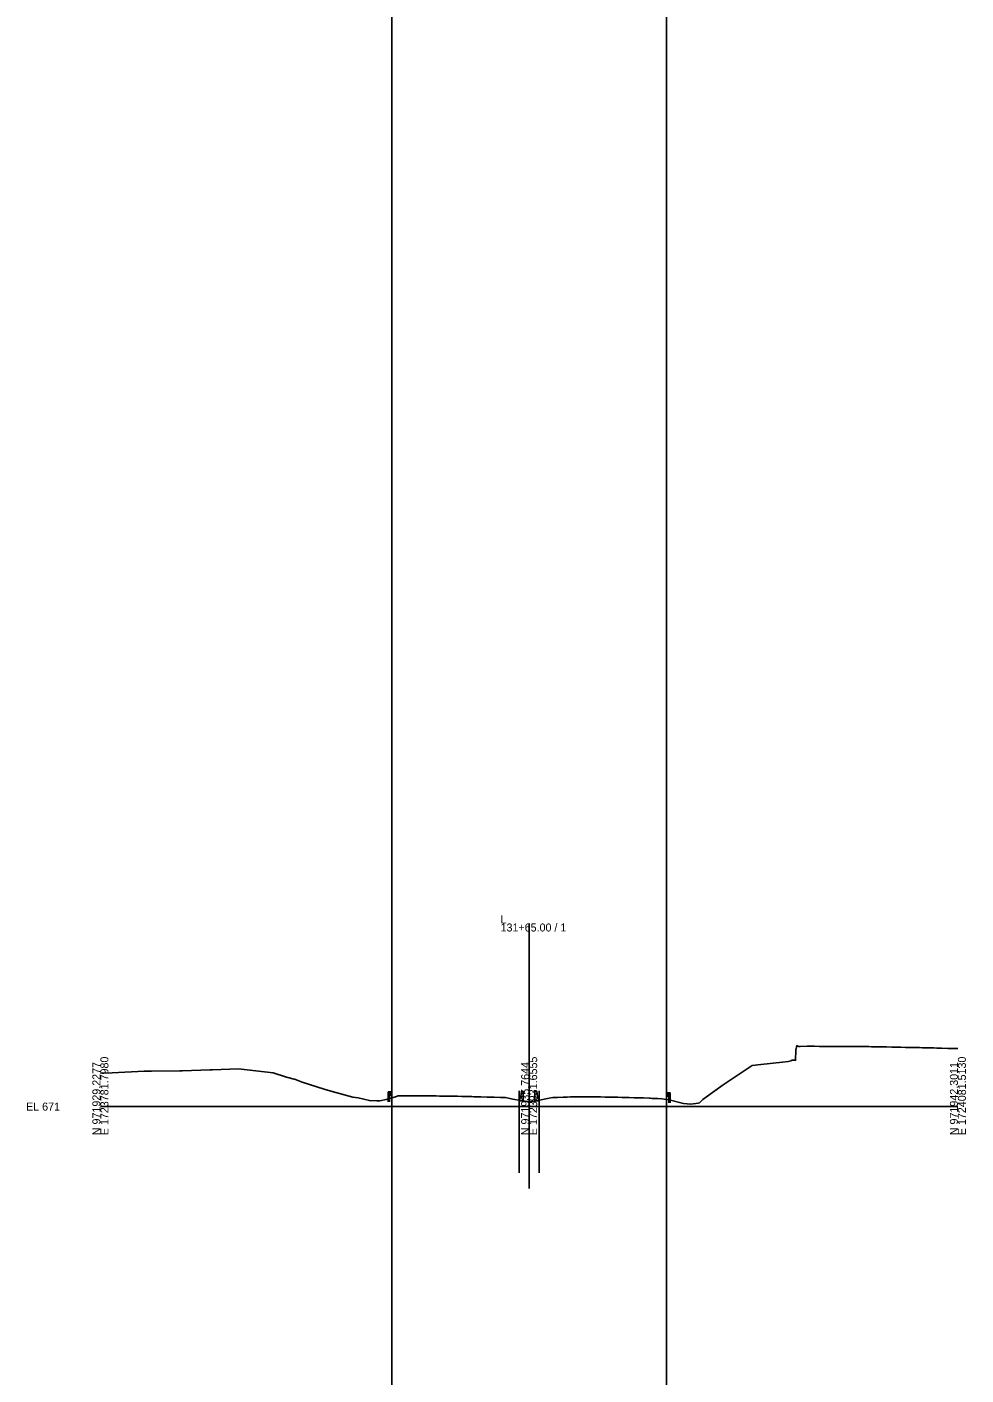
# Model space of a CAD drawing. Extents: x -26 to 303, y -29 to 15026.
# Drawn here: x -25.7 to 302.8, y 5906.1 to 6377.7 of the extents above; entities that cross this region are included whole.
import ezdxf

# ---------------------------------------------------------------- set-up
doc = ezdxf.new("R2010")
doc.units = 0
for name, color, linetype in [('Exist Cross Section Cell', 7, 'Continuous'), ('Exist XS Center Line Elevation Label', 7, 'Continuous'), ('Exist XS Ground Line', 7, 'Continuous'), ('Scratch_Level_0', 7, 'Continuous'), ('Typical Guardrail CELL', 7, 'Continuous'), ('Typical Median Barrier CELL', 7, 'Continuous')]:
    doc.layers.add(name, color=color, linetype=linetype)

msp = doc.modelspace()

# ---------------------------------------------------------------- linework, layer by layer
at = {"layer": 'Exist Cross Section Cell'}
for p, q in [((150, 6000), (150, 6064.05)), ((0, 6000), (150, 6000)), ((150, 6000), (300, 6000))]:
    msp.add_line(p, q, dxfattribs=at)
at = {"layer": 'Exist XS Ground Line'}
msp.add_lwpolyline([(0, 6011.68), (4.14, 6011.84), (15.31, 6012.44), (17.82, 6012.43), (27.8, 6012.49), (28.24, 6012.51), (28.72, 6012.54), (38.25, 6012.82), (39.19, 6012.85), (48.26, 6013.23), (51.3, 6012.91), (60.43, 6011.87), (65.15, 6010.32), (68.28, 6009.45), (70.58, 6008.59), (78.29, 6006.1), (81.05, 6005.3), (88.29, 6003.29), (90.14, 6003.1), (94.14, 6002.12), (96.69, 6001.96), (97.71, 6001.99), (99.94, 6002.52), (103.23, 6003.42), (104.12, 6003.71), (104.95, 6003.78), (105.63, 6003.79), (107.4, 6003.79), (109.09, 6003.78), (109.93, 6003.78), (110.74, 6003.78), (111.28, 6003.78), (111.68, 6003.78), (112.43, 6003.77), (113.47, 6003.75), (114.93, 6003.73), (116.07, 6003.72), (117.42, 6003.71), (118.66, 6003.7), (119.91, 6003.68), (121.26, 6003.66), (122.4, 6003.65), (123.06, 6003.64), (123.92, 6003.62), (124.9, 6003.61), (126.49, 6003.56), (127.4, 6003.54), (129.13, 6003.5), (129.91, 6003.48), (130.62, 6003.46), (132.43, 6003.42), (133.04, 6003.4), (135.18, 6003.34), (135.74, 6003.32), (137.06, 6003.29), (137.41, 6003.28), (137.77, 6003.27), (139.98, 6003.21), (140.87, 6003.17), (141.71, 6003.14), (144.25, 6002.65), (146.95, 6002.12), (150.25, 6001.63), (152.49, 6001.99), (157.02, 6002.92), (158.29, 6003.18), (158.6, 6003.19), (159.23, 6003.21), (159.93, 6003.23), (161.84, 6003.29), (162.45, 6003.3), (163.33, 6003.33), (164.47, 6003.36), (164.95, 6003.36), (166.65, 6003.36), (167.49, 6003.36), (168.39, 6003.37), (169.97, 6003.38), (171.41, 6003.37), (172.48, 6003.37), (173.63, 6003.37), (174.98, 6003.37), (176.54, 6003.35), (177.26, 6003.34), (177.99, 6003.32), (179.96, 6003.27), (180.99, 6003.25), (182.45, 6003.22), (183.37, 6003.19), (184.96, 6003.16), (186.69, 6003.12), (187.46, 6003.1), (189.45, 6003.05), (189.96, 6003.02), (191.93, 6002.93), (192.47, 6002.91), (192.95, 6002.89), (194.97, 6002.79), (196.47, 6002.7), (197.22, 6002.63), (198.03, 6002.53), (198.98, 6002.39), (203.52, 6001.18), (203.94, 6001.13), (206.54, 6000.91), (209.07, 6001.26), (209.54, 6001.36), (210.78, 6002.47), (211.19, 6002.81), (217.83, 6007.6), (220.32, 6009.29), (227.96, 6014.33), (231.06, 6014.68), (238.66, 6015.58), (240.61, 6015.77), (241.68, 6016.02), (241.78, 6016.24), (243.21, 6016.23), (243.29, 6019.79), (243.61, 6021.35), (243.99, 6021.19), (244.31, 6021.03), (244.86, 6021.05), (247.28, 6021.09), (249.86, 6021.1), (251.56, 6021.08), (252.29, 6021.08), (254.96, 6021.07), (257.31, 6021.07), (259.46, 6021.07), (259.8, 6021.07), (260.71, 6021.06), (261.11, 6021.06), (261.65, 6021.06), (262.59, 6021.05), (263.06, 6021.05), (265.1, 6021.03), (265.57, 6021.02), (267.42, 6021), (268.88, 6020.98), (269.82, 6020.96), (270.52, 6020.96), (271.84, 6020.93), (272.56, 6020.91), (273.03, 6020.9), (275.05, 6020.86), (276.9, 6020.82), (277.55, 6020.81), (279.3, 6020.77), (280.05, 6020.76), (281.71, 6020.72), (282.55, 6020.71), (284.11, 6020.67), (285.06, 6020.66), (286.52, 6020.63), (287.57, 6020.6), (288.09, 6020.59), (289.45, 6020.56), (290.65, 6020.54), (291.53, 6020.52), (292.57, 6020.49), (293.09, 6020.48), (294.2, 6020.44), (296.44, 6020.37), (297.79, 6020.33), (298.45, 6020.32), (300, 6020.29)], dxfattribs=at)
at = {"layer": 'Scratch_Level_0'}
for p, q in [((102, 15009.56), (102, -28.7)), ((198, 15009.56), (198, -28.7)), ((146.46, 6005.5), (146.46, 5976.8)), ((153.54, 6005.5), (153.54, 5976.8)), ((150, 6000), (150, 5971.3)), ((150, 6000), (150, 5971.3))]:
    msp.add_line(p, q, dxfattribs=at)
at = {"layer": 'Typical Guardrail CELL'}
for p, q in [((101.18, 6005.21), (100.68, 6005.21)), ((100.68, 6005.21), (100.68, 6002.73)), ((101.18, 6005.21), (101.18, 6002.73)), ((101.18, 6005.21), (101.68, 6005.21)), ((101.18, 6004.05), (101.68, 6004.05)), ((101.68, 6005.21), (101.68, 6004.05)), ((101.68, 6005.21), (101.97, 6005.01)), ((101.68, 6004.68), (101.97, 6004.88)), ((101.68, 6004.63), (101.68, 6004.68)), ((101.68, 6004.63), (101.68, 6004.59)), ((101.68, 6004.59), (101.97, 6004.38)), ((101.68, 6004.05), (101.97, 6004.26)), ((198.32, 6004.78), (198.03, 6004.58)), ((198.32, 6004.25), (198.03, 6004.45)), ((198.32, 6004.15), (198.03, 6003.95)), ((198.32, 6003.62), (198.03, 6003.82)), ((198.82, 6004.78), (198.32, 6004.78)), ((198.32, 6004.78), (198.32, 6003.62)), ((198.32, 6004.2), (198.32, 6004.25)), ((198.32, 6004.2), (198.32, 6004.15)), ((198.82, 6003.62), (198.32, 6003.62)), ((198.82, 6004.78), (198.82, 6002.3)), ((198.82, 6004.78), (199.32, 6004.78)), ((199.32, 6004.78), (199.32, 6002.3)), ((101.18, 6002.73), (100.68, 6002.73)), ((100.68, 6002.73), (100.68, 6001.72)), ((101.18, 6002.73), (101.18, 6001.72)), ((198.82, 6002.3), (199.32, 6002.3)), ((198.82, 6002.3), (198.82, 6001.29)), ((199.32, 6002.3), (199.32, 6001.29))]:
    msp.add_line(p, q, dxfattribs=at)
for centre, start, end in [((101.92, 6004.95), 304.9888, 54.997), ((101.92, 6004.32), 304.9634, 54.9941), ((198.08, 6004.51), 125.003, 235.0112), ((198.08, 6003.89), 125.0059, 235.0366)]:
    msp.add_arc(centre, 0.0776, start, end, dxfattribs=at)
at = {"layer": 'Typical Median Barrier CELL'}
for p, q in [((146.46, 6002.43), (146.92, 6003.08)), ((147.07, 6003.47), (147.29, 6005.43)), ((147.29, 6005.43), (147.96, 6005.43)), ((147.96, 6005.43), (147.96, 6002.01)), ((152.71, 6005.43), (152.04, 6005.43)), ((152.04, 6005.43), (152.04, 6002.01)), ((152.93, 6003.47), (152.71, 6005.43)), ((153.54, 6002.43), (153.08, 6003.08)), ((146.46, 6002.01), (146.46, 6002.43)), ((147.96, 6002.01), (146.46, 6002.01)), ((152.04, 6002.01), (153.54, 6002.01)), ((153.54, 6002.01), (153.54, 6002.43))]:
    msp.add_line(p, q, dxfattribs=at)
for centre, start, end in [((146.24, 6003.56), 325.0039, 353.9447), ((153.76, 6003.56), 186.0553, 214.9961)]:
    msp.add_arc(centre, 0.833, start, end, dxfattribs=at)

# ---------------------------------------------------------------- texts
at = {"layer": 'Exist Cross Section Cell'}
for s, p in [('131+65.00 / 1', (140, 6061.25)), ('L', (140, 6064.05)), ('EL 671', (-26, 5998.6))]:
    msp.add_text(s, height=2.8, dxfattribs=at).set_placement(p)
for s, p in [('E 1723781.7980', (2.8, 5990)), ('E 1723931.6555', (152.8, 5990)), ('E 1724081.5130', (302.8, 5990)), ('N 971929.2277', (0, 5990)), ('N 971935.7644', (150, 5990)), ('N 971942.3011', (300, 5990))]:
    msp.add_text(s, height=2.8, rotation=90, dxfattribs=at).set_placement(p)
at = {"layer": 'Exist XS Center Line Elevation Label'}
msp.add_text('672.67', height=0.18, dxfattribs=at).set_placement((149.61, 6001.18))

doc.saveas('drawing.dxf')
